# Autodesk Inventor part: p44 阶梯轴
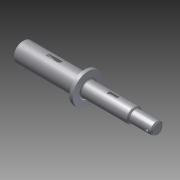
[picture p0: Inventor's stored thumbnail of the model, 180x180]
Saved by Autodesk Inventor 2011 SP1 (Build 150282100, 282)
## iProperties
Created: 2014-01
Part Number: p44 阶梯轴
Document SubType Name: Modeling
Designer: Administrator
Density: 1 g/cm^3
Author: Administrator
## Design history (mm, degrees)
sketch "草图1"
  geometry: L1 (0, 0)-(0, -10); L2 (0, -10)-(1.413, -11.415); L3 (1.413, -11.415)-(0.706, -10.708); L4 (1.413, -11.415)-(74.413, -11.415); L5 (74.413, -11.415)-(74.413, -18.205); L6 (74.413, -18.205)-(78.413, -18.205); L7 (78.413, -18.205)-(78.413, -8.8); L8 (78.413, -8.8)-(133.413, -8.8); L9 (133.413, -8.8)-(135.029, -7.188); L10 (135.029, -7.188)-(160.029, -7.188); L11 (160.029, -7.188)-(161.444, -5.775); L12 (161.444, -5.775)-(161.444, 0); L13 (161.444, 0)-(0, 0)
  constraints: 26 end point, 5 parallel, 5 perpendicular, 1 midpoint, 1 vertical
  dimensions: "d0" = 10 distance of L1.start L1.end; "d1" = 2 distance of L1.end L2.end; "d2" = 73 distance of L2.end L4.end; "d3" = 4 distance of L5.end L6.end; "d4" = 55 distance of L7.end L8.end; "d5" = 25 distance of L9.end L10.end; "d6" = 2 distance of L10.end L11.end
revolve "旋转1" sketch "草图1" stored, may be unused: angle "d7" = 90 deg
fillet "圆角1" dims "d8" = 2
fillet "圆角2" dims "d9" = 2
sketch "草图2"
  geometry: L1 (-160.029, -7.188)-(-135.029, -7.188) reference; L2 (-160.029, 7.188)-(-135.029, 7.188) reference; L3 (0, -10)-(0, 10) reference; C1 r 2 at (-155.283, 0); 1 further point
  constraints: 1 centre point
  dimensions: "d10" = 4 diameter of C1
extrude "拉伸1" cut sketch "草图2" stored distance "d11" = 10; taper "d12" = 0 deg
sketch "草图3"
  geometry: L1 (-133.413, -8.8)-(-80.413, -8.8) reference; L2 (-133.413, 8.8)-(-80.413, 8.8) reference; L3 (-102.508, 8.8)-(-114.135, 8.8); L4 (-114.135, 8.8)-(-114.135, 5.961); L5 (-114.135, 5.961)-(-102.508, 5.961); L6 (-102.508, 5.961)-(-102.508, 8.8); 1 further point
  constraints: 8 end point, 2 parallel, 1 horizontal, 1 perpendicular, 1 point on line
extrude "拉伸2" cut sketch "草图3" stored distance "d13" = 4; taper "d14" = 0 deg
sketch "草图4"
  geometry: L1 (-72.413, 11.415)-(-1.413, 11.415) reference; L2 (-72.413, -11.415)-(-1.413, -11.415) reference; L3 (-29.758, 11.415)-(-46.615, 11.415); A1 r 10.781 centre (-38.186, 18.138) between (-46.615, 11.415) and (-29.758, 11.415); 1 further point
  constraints: 2 end point, 2 point on circle, 2 point on line, 1 centre point
extrude "拉伸3" cut sketch "草图4" stored distance "d15" = 4; taper "d16" = 0 deg
node "实体1"
